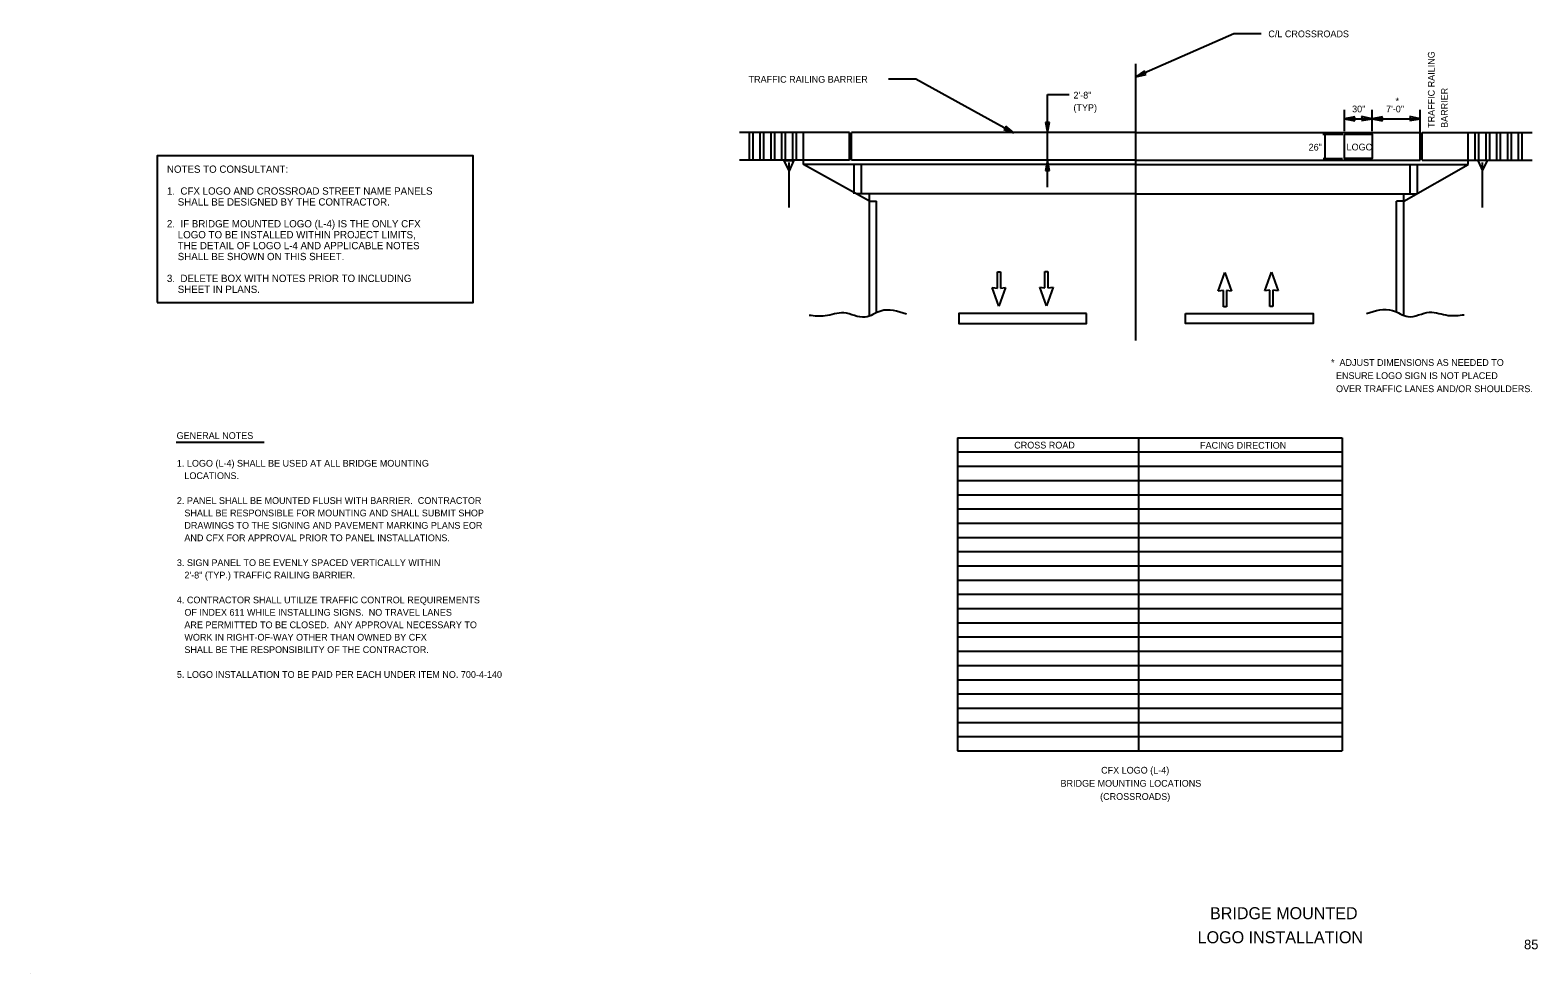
# Model space of a CAD drawing. Extents: x 53062 to 53689, y 9298 to 9690.
import ezdxf

# ---------------------------------------------------------------- set-up
doc = ezdxf.new("R2010")
doc.units = 0
for name, color, linetype in [('AdhocPoint_dp', 7, 'Continuous'), ('Bridge', 7, 'Continuous'), ('CLConst_dp', 7, 'Continuous'), ('Concrete', 7, 'Continuous'), ('DimLines_dp', 7, 'Continuous'), ('DirArrowsPavt', 7, 'Continuous'), ('Grass', 7, 'Continuous'), ('SignPanel', 7, 'Continuous'), ('TextAlert', 7, 'Continuous'), ('TextLabel', 7, 'Continuous'), ('TextMisc', 7, 'Continuous'), ('TextNotes', 7, 'Continuous'), ('TextShtNo', 7, 'Continuous'), ('TextTables', 7, 'Continuous')]:
    doc.layers.add(name, color=color, linetype=linetype)

msp = doc.modelspace()

# ---------------------------------------------------------------- linework, layer by layer
at = {"layer": 'AdhocPoint_dp'}
msp.add_line((53062.39, 9298.05), (53062.39, 9298.05), dxfattribs=at)
at = {"layer": 'Bridge'}
for p, q in [((53402.74, 9647.53), (53357.08, 9647.53)), ((53361.17, 9636.03), (53361.17, 9647.53)), ((53362.67, 9636.03), (53362.67, 9647.53)), ((53365.67, 9636.03), (53365.67, 9647.53)), ((53367.17, 9636.03), (53367.17, 9647.53)), ((53370.17, 9636.03), (53370.17, 9647.53)), ((53371.67, 9636.03), (53371.67, 9647.53)), ((53374.67, 9636.03), (53374.67, 9647.53)), ((53376.17, 9636.03), (53376.17, 9647.53)), ((53379.17, 9636.03), (53379.17, 9647.53)), ((53380.67, 9636.03), (53380.67, 9647.53)), ((53383.67, 9634.25), (53383.67, 9647.53)), ((53402.74, 9636.03), (53402.74, 9647.53)), ((53403.52, 9636.03), (53403.52, 9647.53)), ((53521.67, 9647.53), (53403.52, 9647.53)), ((53521.67, 9647.53), (53639.83, 9647.53)), ((53639.83, 9636.03), (53639.83, 9647.53)), ((53640.6, 9636.03), (53640.6, 9647.53)), ((53640.6, 9647.53), (53686.26, 9647.53)), ((53659.67, 9634.25), (53659.67, 9647.53)), ((53662.67, 9636.03), (53662.67, 9647.53)), ((53664.17, 9636.03), (53664.17, 9647.53)), ((53667.17, 9636.03), (53667.17, 9647.53)), ((53668.67, 9636.03), (53668.67, 9647.53)), ((53671.67, 9636.03), (53671.67, 9647.53)), ((53673.17, 9636.03), (53673.17, 9647.53)), ((53676.17, 9636.03), (53676.17, 9647.53)), ((53677.67, 9636.03), (53677.67, 9647.53)), ((53680.67, 9636.03), (53680.67, 9647.53)), ((53682.17, 9636.03), (53682.17, 9647.53)), ((53402.74, 9636.03), (53357.08, 9636.03)), ((53377.61, 9631.66), (53375.56, 9636.01)), ((53375.56, 9636.01), (53379.15, 9636.01)), ((53379.41, 9635.76), (53377.61, 9631.66)), ((53377.63, 9616.47), (53377.63, 9635.17)), ((53379.15, 9636.01), (53379.41, 9635.76)), ((53411, 9619.07), (53383.67, 9634.25)), ((53484.95, 9634.25), (53383.67, 9634.25)), ((53521.67, 9636.03), (53403.52, 9636.03)), ((53404.67, 9622.08), (53404.67, 9634.25)), ((53407.67, 9622.08), (53407.67, 9634.25)), ((53521.67, 9634.25), (53485.02, 9634.25)), ((53521.67, 9636.03), (53639.83, 9636.03)), ((53521.67, 9634.25), (53659.67, 9634.25)), ((53632.99, 9619.07), (53659.67, 9634.25)), ((53635.67, 9622.08), (53635.67, 9634.25)), ((53638.67, 9622.3), (53638.67, 9634.25)), ((53640.6, 9636.03), (53686.26, 9636.03)), ((53664.19, 9635.98), (53663.93, 9635.73)), ((53663.93, 9635.73), (53665.72, 9631.63)), ((53667.77, 9635.98), (53664.19, 9635.98)), ((53665.72, 9631.63), (53667.77, 9635.98)), ((53665.72, 9616.47), (53665.72, 9635.17)), ((53521.99, 9622.08), (53405.58, 9622.08)), ((53410.99, 9571.37), (53410.99, 9622.08)), ((53521.99, 9622.08), (53638.28, 9622.08)), ((53632.99, 9619.08), (53632.99, 9622.08)), ((53411, 9619.07), (53413.99, 9619.08)), ((53413.99, 9573.1), (53413.99, 9619.08)), ((53629.99, 9573.36), (53629.99, 9619.08)), ((53632.99, 9619.07), (53629.99, 9619.08)), ((53632.99, 9571.63), (53632.99, 9619.08))]:
    msp.add_line(p, q, dxfattribs=at)
at = {"layer": 'CLConst_dp'}
msp.add_line((53521.67, 9561.12), (53521.67, 9676.08), dxfattribs=at)
at = {"layer": 'Concrete'}
for points in [[(53501.23, 9572.38), (53448.21, 9572.38), (53448.21, 9568.28), (53501.23, 9568.28)], [(53542.25, 9572.38), (53595.27, 9572.38), (53595.27, 9568.28), (53542.25, 9568.28)]]:
    msp.add_lwpolyline(points, close=True, dxfattribs=at)
at = {"layer": 'DimLines_dp'}
for p, q in [((53484.98, 9663.31), (53494.03, 9663.31)), ((53484.98, 9647.58), (53484.98, 9663.31)), ((53484.98, 9651.6), (53484.17, 9651.93)), ((53484.17, 9651.93), (53484.98, 9647.58)), ((53484.98, 9651.6), (53484.17, 9651.93)), ((53484.17, 9651.93), (53484.98, 9647.58)), ((53484.98, 9647.58), (53485.82, 9651.93)), ((53485.82, 9651.93), (53484.98, 9651.6)), ((53484.98, 9647.58), (53485.82, 9651.93)), ((53485.82, 9651.93), (53484.98, 9651.6)), ((53608.28, 9648.18), (53608.28, 9657.05)), ((53612.63, 9654.12), (53608.28, 9653.32)), ((53612.63, 9654.12), (53608.28, 9653.32)), ((53608.28, 9653.32), (53619.79, 9653.32)), ((53608.28, 9653.32), (53612.63, 9652.48)), ((53608.28, 9653.32), (53612.63, 9652.48)), ((53612.3, 9653.32), (53612.63, 9654.12)), ((53612.3, 9653.32), (53612.63, 9654.12)), ((53612.63, 9652.48), (53612.3, 9653.32)), ((53612.63, 9652.48), (53612.3, 9653.32)), ((53619.79, 9653.32), (53615.44, 9654.16)), ((53615.44, 9654.16), (53615.77, 9653.32)), ((53619.79, 9653.32), (53615.44, 9654.16)), ((53615.44, 9654.16), (53615.77, 9653.32)), ((53615.77, 9653.32), (53615.44, 9652.51)), ((53615.44, 9652.51), (53619.79, 9653.32)), ((53615.77, 9653.32), (53615.44, 9652.51)), ((53615.44, 9652.51), (53619.79, 9653.32)), ((53619.79, 9648.18), (53619.79, 9657.05)), ((53624.14, 9654.12), (53619.79, 9653.32)), ((53624.14, 9654.12), (53619.79, 9653.32)), ((53619.79, 9653.32), (53639.83, 9653.32)), ((53619.79, 9653.32), (53624.14, 9652.48)), ((53619.79, 9653.32), (53624.14, 9652.48)), ((53623.81, 9653.32), (53624.14, 9654.12)), ((53623.81, 9653.32), (53624.14, 9654.12)), ((53624.14, 9652.48), (53623.81, 9653.32)), ((53624.14, 9652.48), (53623.81, 9653.32)), ((53639.83, 9653.32), (53635.48, 9654.16)), ((53635.48, 9654.16), (53635.81, 9653.32)), ((53635.81, 9653.32), (53635.48, 9652.51)), ((53635.48, 9652.51), (53639.83, 9653.32)), ((53639.83, 9647.53), (53639.83, 9657.05)), ((53484.98, 9634.25), (53484.98, 9647.58)), ((53599.29, 9646.83), (53607.63, 9646.83)), ((53600.31, 9636.49), (53600.31, 9646.94)), ((53484.98, 9636.03), (53484.14, 9631.68)), ((53484.14, 9631.68), (53484.98, 9632.01)), ((53484.98, 9624.91), (53484.98, 9636.03)), ((53485.79, 9631.68), (53484.98, 9636.03)), ((53484.98, 9632.01), (53485.79, 9631.68)), ((53599.49, 9636.75), (53607.58, 9636.75))]:
    msp.add_line(p, q, dxfattribs=at)
at = {"layer": 'DirArrowsPavt'}
for p, q in [((53464.18, 9589.7), (53465.42, 9589.7)), ((53464.18, 9582.95), (53464.18, 9589.7)), ((53465.42, 9589.7), (53465.42, 9582.95)), ((53483.9, 9589.83), (53485.15, 9589.83)), ((53483.9, 9583.08), (53483.9, 9589.83)), ((53485.15, 9589.83), (53485.15, 9583.08)), ((53555.92, 9581.69), (53558.66, 9589.42)), ((53558.66, 9589.42), (53561.41, 9581.69)), ((53575.25, 9581.82), (53578, 9589.55)), ((53578, 9589.55), (53580.75, 9581.82)), ((53464.8, 9575.45), (53462.05, 9583.18)), ((53462.05, 9583.18), (53464.18, 9582.95)), ((53467.55, 9583.18), (53464.8, 9575.45)), ((53465.42, 9582.95), (53467.55, 9583.18)), ((53484.52, 9575.58), (53481.77, 9583.31)), ((53481.77, 9583.31), (53483.9, 9583.08)), ((53487.27, 9583.31), (53484.52, 9575.58)), ((53485.15, 9583.08), (53487.27, 9583.31)), ((53558.04, 9581.92), (53555.92, 9581.69)), ((53558.04, 9575.17), (53558.04, 9581.92)), ((53561.41, 9581.69), (53559.29, 9581.92)), ((53559.29, 9581.92), (53559.29, 9575.17)), ((53577.38, 9582.05), (53575.25, 9581.82)), ((53577.38, 9575.3), (53577.38, 9582.05)), ((53580.75, 9581.82), (53578.63, 9582.05)), ((53578.63, 9582.05), (53578.63, 9575.3)), ((53559.29, 9575.17), (53558.04, 9575.17)), ((53578.63, 9575.3), (53577.38, 9575.3))]:
    msp.add_line(p, q, dxfattribs=at)
at = {"layer": 'Grass'}
for points in [[(53426.44, 9572.12), (53415.68, 9573.4), (53409.28, 9570.84), (53400.31, 9572.64), (53392.63, 9571.35), (53385.97, 9571.61)], [(53617.55, 9572.38), (53628.31, 9573.66), (53634.71, 9571.09), (53643.68, 9572.89), (53651.36, 9571.61), (53658.02, 9571.86)]]:
    msp.add_spline(points, degree=3, dxfattribs=at)
at = {"layer": 'SignPanel'}
msp.add_lwpolyline([(53608.28, 9646.83), (53619.78, 9646.83), (53619.78, 9636.75), (53608.28, 9636.75)], close=True, dxfattribs=at)
at = {"layer": 'TextAlert'}
msp.add_lwpolyline([(53115.2, 9576.94), (53246.46, 9576.94), (53246.46, 9637.86), (53115.2, 9637.86)], close=True, dxfattribs=at)
at = {"layer": 'TextLabel'}
for p, q in [((53562.43, 9688.6), (53521.67, 9670.67)), ((53573.7, 9688.6), (53562.43, 9688.6)), ((53418.98, 9669.81), (53430.25, 9669.81)), ((53430.25, 9669.81), (53471, 9647.4)), ((53525.33, 9673.17), (53521.67, 9670.67)), ((53521.67, 9670.67), (53525.99, 9671.66)), ((53525.35, 9672.29), (53525.33, 9673.17)), ((53525.99, 9671.66), (53525.35, 9672.29)), ((53467.48, 9649.34), (53466.8, 9648.79)), ((53467.48, 9649.34), (53466.8, 9648.79)), ((53466.8, 9648.79), (53471, 9647.4)), ((53466.8, 9648.79), (53471, 9647.4)), ((53467.6, 9650.23), (53467.48, 9649.34)), ((53467.6, 9650.23), (53467.48, 9649.34)), ((53471, 9647.4), (53467.6, 9650.23)), ((53471, 9647.4), (53467.6, 9650.23))]:
    msp.add_line(p, q, dxfattribs=at)
at = {"layer": 'TextNotes'}
msp.add_line((53122.98, 9518.92), (53159.57, 9518.92), dxfattribs=at)
at = {"layer": 'TextTables'}
for p, q in [((53447.62, 9520.76), (53607.31, 9520.76)), ((53447.62, 9520.76), (53447.62, 9390.7)), ((53522.91, 9390.7), (53522.91, 9520.76)), ((53607.31, 9520.76), (53607.31, 9390.7)), ((53447.62, 9514.85), (53607.31, 9514.85)), ((53447.62, 9508.94), (53607.31, 9508.94)), ((53447.62, 9503.03), (53607.31, 9503.03)), ((53447.62, 9497.11), (53607.31, 9497.11)), ((53447.63, 9491.2), (53607.31, 9491.2)), ((53447.62, 9485.29), (53607.31, 9485.29)), ((53447.62, 9479.38), (53607.31, 9479.38)), ((53447.62, 9473.47), (53607.31, 9473.47)), ((53447.62, 9467.56), (53607.31, 9467.56)), ((53447.62, 9461.64), (53607.31, 9461.64)), ((53447.62, 9455.73), (53607.31, 9455.73)), ((53447.62, 9449.82), (53607.31, 9449.82)), ((53447.62, 9443.91), (53607.31, 9443.91)), ((53447.62, 9437.99), (53607.31, 9437.99)), ((53447.62, 9432.08), (53607.31, 9432.08)), ((53447.62, 9426.17), (53607.31, 9426.17)), ((53447.62, 9420.26), (53607.31, 9420.26)), ((53447.62, 9414.35), (53607.31, 9414.35)), ((53447.62, 9408.43), (53607.31, 9408.43)), ((53447.62, 9402.52), (53607.31, 9402.52)), ((53447.62, 9396.61), (53607.31, 9396.61)), ((53447.62, 9390.7), (53607.31, 9390.7))]:
    msp.add_line(p, q, dxfattribs=at)

# ---------------------------------------------------------------- texts
at = {"layer": 'DimLines_dp'}
for s, p in [('2\'-8"', (53495.76, 9661.68)), ('(TYP)', (53495.76, 9656.51)), ('30"', (53611.5, 9655.96)), ('7\'-0"', (53625.6, 9655.95)), ('*', (53629.53, 9659.27)), ('26"', (53593.45, 9640.07))]:
    msp.add_text(s, height=2.8, dxfattribs=at).set_placement(p)
at = {"layer": 'TextAlert'}
for s, p in [('NOTES TO CONSULTANT:', (53119.2, 9630.84)), ('1.  CFX LOGO AND CROSSROAD STREET NAME PANELS', (53119.2, 9621.76)), ('    SHALL BE DESIGNED BY THE CONTRACTOR.', (53119.2, 9617.23)), ('2.  IF BRIDGE MOUNTED LOGO (L-4) IS THE ONLY CFX', (53119.2, 9608.16)), ('    THE DETAIL OF LOGO L-4 AND APPLICABLE NOTES', (53119.2, 9599.08)), ('    LOGO TO BE INSTALLED WITHIN PROJECT LIMITS,', (53119.2, 9603.62)), ('    SHALL BE SHOWN ON THIS SHEET.', (53119.2, 9594.55)), ('3.  DELETE BOX WITH NOTES PRIOR TO INCLUDING', (53119.2, 9585.48)), ('    SHEET IN PLANS.', (53119.2, 9580.94))]:
    msp.add_text(s, height=3.024, dxfattribs=at).set_placement(p)
at = {"layer": 'TextLabel'}
for s, p in [('C/L CROSSROADS', (53576.71, 9687.15)), ('TRAFFIC RAILING BARRIER', (53360.81, 9668.26)), ('LOGO ', (53609.21, 9640.13))]:
    msp.add_text(s, height=2.8, dxfattribs=at).set_placement(p)
for s, p in [('TRAFFIC RAILING ', (53645.79, 9649.49)), ('BARRIER', (53651.25, 9649.49))]:
    msp.add_text(s, height=2.8, rotation=90, dxfattribs=at).set_placement(p)
at = {"layer": 'TextMisc'}
for s, p in [('     BRIDGE MOUNTED     ', (53543.2, 9320.75)), ('   LOGO INSTALLATION    ', (53541.77, 9310.75))]:
    msp.add_text(s, height=5, rotation=360, dxfattribs=at).set_placement(p)
at = {"layer": 'TextNotes'}
for s, p in [('*  ADJUST DIMENSIONS AS NEEDED TO', (53602.74, 9550.62)), ('  ENSURE LOGO SIGN IS NOT PLACED', (53602.74, 9545.17)), ('  OVER TRAFFIC LANES AND/OR SHOULDERS.', (53602.74, 9539.71)), ('GENERAL NOTES', (53123.23, 9520.26)), ('1. LOGO (L-4) SHALL BE USED AT ALL BRIDGE MOUNTING', (53123.34, 9508.76)), ('   LOCATIONS.', (53123.34, 9503.6)), ('2. PANEL SHALL BE MOUNTED FLUSH WITH BARRIER.  CONTRACTOR', (53123.34, 9493.27)), ('   SHALL BE RESPONSIBLE FOR MOUNTING AND SHALL SUBMIT SHOP', (53123.34, 9488.11)), ('   DRAWINGS TO THE SIGNING AND PAVEMENT MARKING PLANS EOR', (53123.34, 9482.95)), ('   AND CFX FOR APPROVAL PRIOR TO PANEL INSTALLATIONS.', (53123.34, 9477.79)), ('3. SIGN PANEL TO BE EVENLY SPACED VERTICALLY WITHIN ', (53123.34, 9467.46)), ('   2\'-8" (TYP.) TRAFFIC RAILING BARRIER.', (53123.34, 9462.3)), ('4. CONTRACTOR SHALL UTILIZE TRAFFIC CONTROL REQUIREMENTS', (53123.34, 9451.98)), ('   ARE PERMITTED TO BE CLOSED.  ANY APPROVAL NECESSARY TO ', (53123.34, 9441.65)), ('   OF INDEX 611 WHILE INSTALLING SIGNS.  NO TRAVEL LANES ', (53123.34, 9446.82)), ('   WORK IN RIGHT-OF-WAY OTHER THAN OWNED BY CFX', (53123.34, 9436.49)), ('   SHALL BE THE RESPONSIBILITY OF THE CONTRACTOR.', (53123.34, 9431.33)), ('5. LOGO INSTALLATION TO BE PAID PER EACH UNDER ITEM NO. 700-4-140', (53123.34, 9421.01))]:
    msp.add_text(s, height=2.8, dxfattribs=at).set_placement(p)
at = {"layer": 'TextShtNo'}
msp.add_text('85', height=4, rotation=360, dxfattribs=at).set_placement((53682.93, 9308.25))
at = {"layer": 'TextTables'}
for s, p in [('CROSS ROAD', (53471.16, 9516.3)), ('FACING DIRECTION', (53548.35, 9516.22)), ('CFX LOGO (L-4)', (53507.25, 9381.24)), ('BRIDGE MOUNTING LOCATIONS ', (53490.39, 9375.79)), ('(CROSSROADS)', (53506.83, 9370.33))]:
    msp.add_text(s, height=2.8, dxfattribs=at).set_placement(p)

doc.saveas('drawing.dxf')
